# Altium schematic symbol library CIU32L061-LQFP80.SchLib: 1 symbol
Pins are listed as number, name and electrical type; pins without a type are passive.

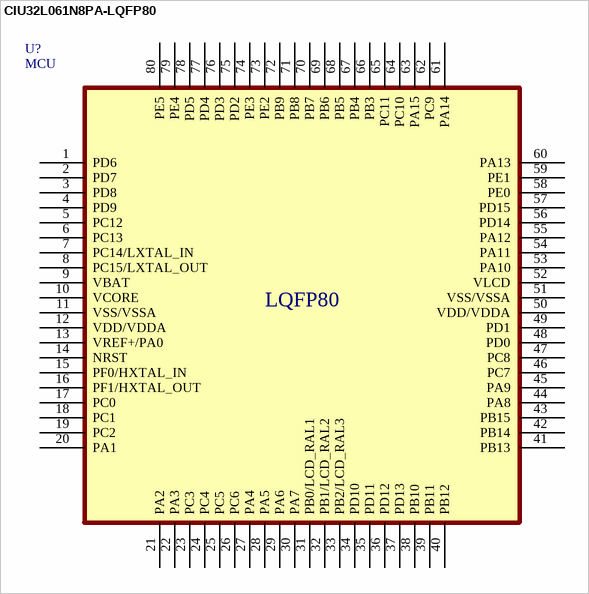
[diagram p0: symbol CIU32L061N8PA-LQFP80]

## CIU32L061N8PA-LQFP80
designator U?, comment MCU
footprint CIU32L061-LQFP_80N
pins: 1 PD6, 2 PD7, 3 PD8, 4 PD9, 5 PC12, 6 PC13, 7 PC14/LXTAL_IN, 8 PC15/LXTAL_OUT, 9 VBAT, 10 VCORE, 11 VSS/VSSA, 12 VDD/VDDA, 13 VREF+/PA0, 14 NRST, 15 PF0/HXTAL_IN, 16 PF1/HXTAL_OUT, 17 PC0, 18 PC1, 19 PC2, 20 PA1, 21 PA2, 22 PA3, 23 PC3, 24 PC4, 25 PC5, 26 PC6, 27 PA4, 28 PA5, 29 PA6, 30 PA7, 31 PB0/LCD_RAL1, 32 PB1/LCD_RAL2, 33 PB2/LCD_RAL3, 34 PD10, 35 PD11, 36 PD12, 37 PD13, 38 PB10, 39 PB11, 40 PB12, 41 PB13, 42 PB14, 43 PB15, 44 PA8, 45 PA9, 46 PC7, 47 PC8, 48 PD0, 49 PD1, 50 VDD/VDDA, 51 VSS/VSSA, 52 VLCD, 53 PA10, 54 PA11, 55 PA12, 56 PD14, 57 PD15, 58 PE0, 59 PE1, 60 PA13, 61 PA14, 62 PC9, 63 PA15, 64 PC10, 65 PC11, 66 PB3, 67 PB4, 68 PB5, 69 PB6, 70 PB7, 71 PB8, 72 PB9, 73 PE2, 74 PE3, 75 PD2, 76 PD3, 77 PD4, 78 PD5, 79 PE4, 80 PE5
